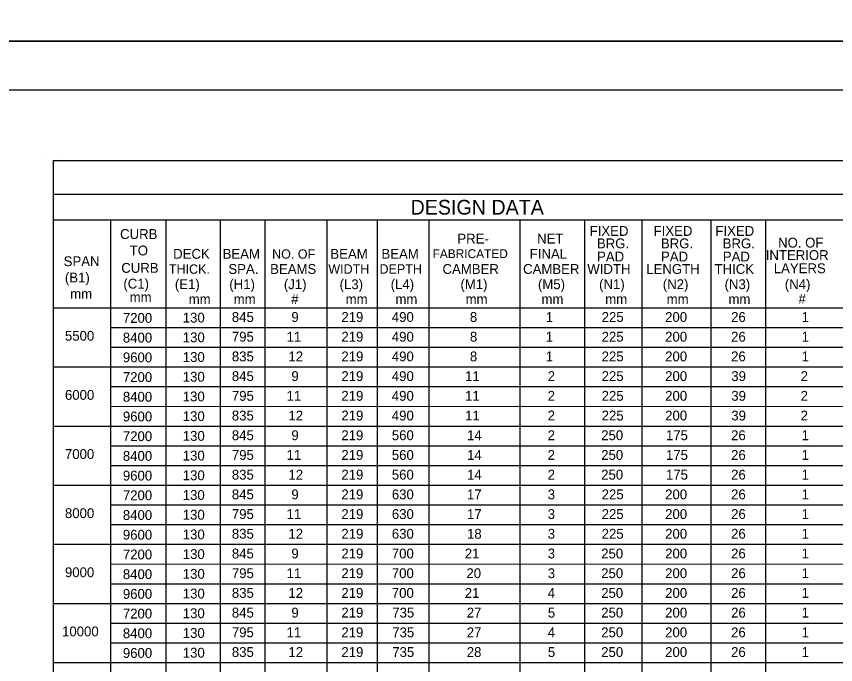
# Model space of a CAD drawing. Extents: x -5022 to -159, y 1126 to 7226.
# Drawn here: x -4612.3 to -4362.8, y 3906 to 4103.3 of the extents above; entities that cross this region are included whole.
import ezdxf

# ---------------------------------------------------------------- set-up
doc = ezdxf.new("R2010")
doc.units = 0
for name, color, linetype in [('2', 7, 'Continuous'), ('3', 7, 'Continuous'), ('PLT-BNDY', 7, 'Continuous')]:
    doc.layers.add(name, color=color, linetype=linetype)

msp = doc.modelspace()

# ---------------------------------------------------------------- linework, layer by layer
at = {"layer": '2'}
for p, q in [((-3855.13, 4080.81), (-4641.13, 4080.81)), ((-4603.08, 4061.37), (-4603.08, 4061.37)), ((-4599.68, 4060.79), (-4599.68, 4060.79))]:
    msp.add_line(p, q, dxfattribs=at)
at = {"layer": '3'}
for p, q in [((-4601.11, 4059.4), (-4601.11, 3708.59)), ((-4601.11, 4059.4), (-3886.2, 4059.4)), ((-4600.86, 4049.23), (-3886.2, 4049.23)), ((-4601.11, 4041.41), (-3886.2, 4041.41)), ((-4583.63, 4041.41), (-4583.63, 3708.59)), ((-4566.84, 4041.41), (-4566.84, 3708.59)), ((-4550.27, 4041.41), (-4550.27, 3708.59)), ((-4536.64, 4041.41), (-4536.64, 3708.59)), ((-4517.79, 4041.41), (-4517.79, 3708.59)), ((-4502.48, 4041.41), (-4502.48, 3708.59)), ((-4486.68, 4041.41), (-4486.68, 3708.59)), ((-4458.97, 4041.41), (-4458.97, 3708.59)), ((-4439.28, 4041.41), (-4439.28, 3708.59)), ((-4421.82, 4041.41), (-4421.82, 3708.59)), ((-4400.82, 4041.41), (-4400.82, 3708.59)), ((-4384.18, 4041.41), (-4384.18, 3708.59)), ((-4601.11, 4014.6), (-3886.2, 4014.6)), ((-4583.63, 4008.6), (-3886.2, 4008.6)), ((-4583.63, 4002.6), (-3886.2, 4002.6)), ((-4601.11, 3996.6), (-3886.2, 3996.6)), ((-4583.63, 3990.59), (-3886.2, 3990.6)), ((-4583.63, 3984.59), (-3886.2, 3984.6)), ((-4601.11, 3978.59), (-3886.2, 3978.6)), ((-4583.63, 3972.59), (-3886.2, 3972.6)), ((-4583.63, 3966.6), (-3886.2, 3966.6)), ((-4601.11, 3960.6), (-3886.2, 3960.6)), ((-4583.63, 3954.59), (-3886.2, 3954.6)), ((-4583.63, 3948.59), (-3886.2, 3948.6)), ((-4601.11, 3942.59), (-3886.2, 3942.6)), ((-4583.63, 3936.59), (-3886.2, 3936.6)), ((-4583.63, 3930.59), (-3886.2, 3930.59)), ((-4601.11, 3924.59), (-3886.2, 3924.59)), ((-4583.63, 3918.59), (-3886.2, 3918.59)), ((-4583.63, 3912.59), (-3886.2, 3912.6)), ((-4601.11, 3906.59), (-3886.2, 3906.59))]:
    msp.add_line(p, q, dxfattribs=at)
at = {"layer": 'PLT-BNDY'}
for points in [[(-4681.13, 4689.81), (-3840.13, 4689.81), (-3840.13, 4095.81), (-4681.13, 4095.81)], [(-4681.13, 4095.81), (-3840.13, 4095.81), (-3840.13, 3501.81), (-4681.13, 3501.81)]]:
    msp.add_lwpolyline(points, close=True, dxfattribs=at)

# ---------------------------------------------------------------- texts
at = {"layer": '2'}
for s, height, p in [('DESIGN DATA', 4.4793, (-4492.26, 4042.97)), ('CURB', 3, (-4580.74, 4035.54)), ('FIXED', 3, (-4437.7, 4036.49)), ('FIXED', 3, (-4418.22, 4036.49)), ('FIXED', 3, (-4399.4, 4036.49)), ('PRE-', 3, (-4478.01, 4034.15)), ('NET', 3, (-4453.71, 4034.15)), ('BRG.', 3, (-4435.49, 4032.7)), ('BRG.', 3, (-4416, 4032.7)), ('BRG.', 3, (-4397.19, 4032.7)), ('NO. OF', 3, (-4380.31, 4032.93)), ('TO', 3, (-4577.81, 4030.54)), ('SPAN', 3, (-4597.93, 4027.27)), ('DECK', 3, (-4564.57, 4029.52)), ('BEAM', 3, (-4549.51, 4029.52)), ('NO. OF', 2.85, (-4534.44, 4029.54)), ('BEAM', 3, (-4516.69, 4029.52)), ('BEAM', 3, (-4501.13, 4029.52)), ('FABRICATED', 2.708, (-4485.56, 4029.72)), ('FINAL', 3, (-4455.96, 4029.52)), ('PAD', 3, (-4435.45, 4028.69)), ('PAD', 3, (-4415.97, 4028.69)), ('PAD', 3, (-4397.15, 4028.69)), ('INTERIOR', 3, (-4384.07, 4029.14)), ('CURB', 3, (-4580.38, 4025.24)), ('THICK.', 2.85, (-4565.87, 4024.95)), ('SPA.', 3, (-4547.76, 4024.9)), ('BEAMS', 3, (-4535.03, 4024.9)), ('WIDTH', 2.85, (-4517.31, 4024.97)), ('DEPTH', 2.85, (-4501.72, 4024.98)), ('CAMBER', 3, (-4482.53, 4024.9)), ('CAMBER', 3, (-4457.98, 4024.9)), ('WIDTH', 3, (-4438.42, 4024.9)), ('LENGTH', 3, (-4420.46, 4024.9)), ('THICK', 3, (-4399.67, 4024.9)), ('LAYERS', 3, (-4381.63, 4025.13)), ('(B1)', 3, (-4597.56, 4022.3)), ('(C1)', 3, (-4579.75, 4020.44)), ('(E1)', 3, (-4564.06, 4020.27)), ('(H1)', 3, (-4547.47, 4020.27)), ('(J1)', 3, (-4530.86, 4020.27)), ('(L3)', 3, (-4513.88, 4020.27)), ('(L4)', 3, (-4498.32, 4020.27)), ('(M1)', 3, (-4477.07, 4020.27)), ('(M5)', 3, (-4453.46, 4020.27)), ('(N1)', 3, (-4434.83, 4020.27)), ('(N2)', 3, (-4415.43, 4020.27)), ('(N3)', 3, (-4396.61, 4020.27)), ('(N4)', 3, (-4378.27, 4020.27)), ('mm', 3, (-4595.94, 4017.33)), ('mm', 3, (-4577.84, 4016.34)), ('mm', 3, (-4559.83, 4015.74)), ('mm', 3, (-4546.13, 4015.74)), ('#', 3, (-4528.62, 4015.74)), ('mm', 3, (-4512.03, 4015.74)), ('mm', 3, (-4496.87, 4015.74)), ('mm', 3, (-4475.5, 4015.74)), ('mm', 3, (-4452.38, 4015.74)), ('mm', 3, (-4432.96, 4015.74)), ('mm', 3, (-4414.25, 4015.74)), ('mm', 3, (-4395.43, 4015.74)), ('#', 3, (-4374.09, 4015.85)), ('7200', 3, (-4579.9, 4010.01)), ('130', 3, (-4561.65, 4010.1)), ('845', 3, (-4546.7, 4010.29)), ('9', 3, (-4528.57, 4010.29)), ('219', 3, (-4513.34, 4010.29)), ('490', 3, (-4497.97, 4010.29)), ('8', 3, (-4474.18, 4010.29)), ('1', 3, (-4451.07, 4010.29)), ('225', 3, (-4434.05, 4010.29)), ('200', 3, (-4414.71, 4010.29)), ('26', 3, (-4394.62, 4010.29)), ('1', 3, (-4373.15, 4010.29)), ('5500', 3, (-4597.54, 4004.57)), ('8400', 3, (-4579.9, 4004.01)), ('130', 3, (-4561.65, 4004.1)), ('795', 3, (-4546.7, 4004.29)), ('11', 3, (-4530.04, 4004.29)), ('219', 3, (-4513.34, 4004.29)), ('490', 3, (-4497.97, 4004.29)), ('8', 3, (-4474.18, 4004.29)), ('1', 3, (-4451.07, 4004.29)), ('225', 3, (-4434.05, 4004.29)), ('200', 3, (-4414.71, 4004.29)), ('26', 3, (-4394.62, 4004.29)), ('1', 3, (-4373.15, 4004.29)), ('9600', 3, (-4579.9, 3998)), ('130', 3, (-4561.65, 3998.1)), ('835', 3, (-4546.7, 3998.29)), ('12', 3, (-4529.46, 3998.29)), ('219', 3, (-4513.34, 3998.29)), ('490', 3, (-4497.97, 3998.29)), ('8', 3, (-4474.18, 3998.29)), ('1', 3, (-4451.07, 3998.29)), ('225', 3, (-4434.05, 3998.29)), ('200', 3, (-4414.71, 3998.29)), ('26', 3, (-4394.62, 3998.29)), ('1', 3, (-4373.15, 3998.29)), ('845', 3, (-4546.7, 3992.29)), ('9', 3, (-4528.57, 3992.29)), ('219', 3, (-4513.34, 3992.29)), ('490', 3, (-4497.97, 3992.29)), ('11', 3, (-4475.65, 3992.29)), ('2', 3, (-4450.5, 3992.29)), ('225', 3, (-4434.05, 3992.29)), ('200', 3, (-4414.71, 3992.29)), ('39', 3, (-4394.56, 3992.29)), ('2', 3, (-4373.43, 3992.29)), ('7200', 3, (-4579.9, 3992)), ('130', 3, (-4561.65, 3992.1)), ('6000', 3, (-4597.54, 3986.57)), ('8400', 3, (-4579.9, 3986)), ('130', 3, (-4561.65, 3986.1)), ('795', 3, (-4546.7, 3986.29)), ('11', 3, (-4530.04, 3986.29)), ('219', 3, (-4513.34, 3986.29)), ('490', 3, (-4497.97, 3986.29)), ('11', 3, (-4475.65, 3986.29)), ('2', 3, (-4450.5, 3986.29)), ('225', 3, (-4434.05, 3986.29)), ('200', 3, (-4414.71, 3986.29)), ('39', 3, (-4394.56, 3986.29)), ('2', 3, (-4373.43, 3986.29)), ('9600', 3, (-4579.9, 3980)), ('130', 3, (-4561.65, 3980.09)), ('835', 3, (-4546.7, 3980.29)), ('12', 3, (-4529.46, 3980.29)), ('219', 3, (-4513.34, 3980.29)), ('490', 3, (-4497.97, 3980.29)), ('11', 3, (-4475.65, 3980.29)), ('2', 3, (-4450.5, 3980.29)), ('225', 3, (-4434.05, 3980.29)), ('200', 3, (-4414.71, 3980.29)), ('39', 3, (-4394.56, 3980.29)), ('2', 3, (-4373.43, 3980.29)), ('7200', 3, (-4579.9, 3974)), ('130', 3, (-4561.65, 3974.1)), ('845', 3, (-4546.7, 3974.29)), ('9', 3, (-4528.57, 3974.29)), ('219', 3, (-4513.34, 3974.29)), ('560', 3, (-4497.97, 3974.29)), ('14', 3, (-4475.05, 3974.29)), ('2', 3, (-4450.5, 3974.29)), ('250', 3, (-4434.19, 3974.29)), ('175', 3, (-4414.47, 3974.29)), ('26', 3, (-4394.62, 3974.29)), ('1', 3, (-4373.15, 3974.29)), ('7000', 3, (-4597.54, 3968.57)), ('8400', 3, (-4579.9, 3968)), ('130', 3, (-4561.65, 3968.1)), ('795', 3, (-4546.7, 3968.29)), ('11', 3, (-4530.04, 3968.29)), ('219', 3, (-4513.34, 3968.29)), ('560', 3, (-4497.97, 3968.29)), ('14', 3, (-4475.05, 3968.29)), ('2', 3, (-4450.5, 3968.29)), ('250', 3, (-4434.19, 3968.29)), ('175', 3, (-4414.47, 3968.29)), ('26', 3, (-4394.62, 3968.29)), ('1', 3, (-4373.15, 3968.29)), ('835', 3, (-4546.7, 3962.29)), ('12', 3, (-4529.46, 3962.29)), ('219', 3, (-4513.34, 3962.29)), ('560', 3, (-4497.97, 3962.29)), ('2', 3, (-4450.5, 3962.29)), ('250', 3, (-4434.19, 3962.29)), ('26', 3, (-4394.62, 3962.29)), ('9600', 3, (-4579.9, 3962)), ('130', 3, (-4561.65, 3962.1)), ('14', 3, (-4475.05, 3962.29)), ('175', 3, (-4414.47, 3962.29)), ('1', 3, (-4373.15, 3962.29)), ('7200', 3, (-4579.9, 3956)), ('130', 3, (-4561.65, 3956.1)), ('845', 3, (-4546.7, 3956.29)), ('9', 3, (-4528.57, 3956.29)), ('219', 3, (-4513.34, 3956.29)), ('630', 3, (-4497.97, 3956.29)), ('17', 3, (-4475.07, 3956.29)), ('3', 3, (-4450.48, 3956.29)), ('225', 3, (-4434.05, 3956.29)), ('200', 3, (-4414.71, 3956.29)), ('26', 3, (-4394.62, 3956.29)), ('1', 3, (-4373.15, 3956.29)), ('8000', 3, (-4597.54, 3950.57)), ('8400', 3, (-4579.9, 3950)), ('130', 3, (-4561.65, 3950.09)), ('795', 3, (-4546.7, 3950.29)), ('11', 3, (-4530.04, 3950.29)), ('219', 3, (-4513.34, 3950.29)), ('630', 3, (-4497.97, 3950.29)), ('17', 3, (-4475.07, 3950.29)), ('3', 3, (-4450.48, 3950.29)), ('225', 3, (-4434.05, 3950.29)), ('200', 3, (-4414.71, 3950.29)), ('26', 3, (-4394.62, 3950.29)), ('1', 3, (-4373.15, 3950.29)), ('9600', 3, (-4579.9, 3944)), ('130', 3, (-4561.65, 3944.09)), ('835', 3, (-4546.7, 3944.29)), ('12', 3, (-4529.46, 3944.29)), ('219', 3, (-4513.34, 3944.29)), ('630', 3, (-4497.97, 3944.29)), ('18', 3, (-4475.06, 3944.29)), ('3', 3, (-4450.48, 3944.29)), ('225', 3, (-4434.05, 3944.29)), ('200', 3, (-4414.71, 3944.29)), ('26', 3, (-4394.62, 3944.29)), ('1', 3, (-4373.15, 3944.29)), ('7200', 3, (-4579.9, 3938)), ('130', 3, (-4561.65, 3938.1)), ('845', 3, (-4546.7, 3938.29)), ('9', 3, (-4528.57, 3938.29)), ('219', 3, (-4513.34, 3938.29)), ('700', 3, (-4497.97, 3938.29)), ('21', 3, (-4475.74, 3938.29)), ('3', 3, (-4450.48, 3938.29)), ('250', 3, (-4434.19, 3938.29)), ('200', 3, (-4414.71, 3938.29)), ('26', 3, (-4394.62, 3938.29)), ('1', 3, (-4373.15, 3938.29)), ('9000', 3, (-4597.54, 3932.57)), ('8400', 3, (-4579.9, 3932)), ('130', 3, (-4561.65, 3932.1)), ('795', 3, (-4546.7, 3932.29)), ('11', 3, (-4530.04, 3932.29)), ('219', 3, (-4513.34, 3932.29)), ('700', 3, (-4497.97, 3932.29)), ('20', 3, (-4475.25, 3932.29)), ('3', 3, (-4450.48, 3932.29)), ('250', 3, (-4434.19, 3932.29)), ('200', 3, (-4414.71, 3932.29)), ('26', 3, (-4394.62, 3932.29)), ('1', 3, (-4373.15, 3932.29)), ('9600', 3, (-4579.9, 3926)), ('130', 3, (-4561.65, 3926.09)), ('835', 3, (-4546.7, 3926.29)), ('12', 3, (-4529.46, 3926.29)), ('219', 3, (-4513.34, 3926.29)), ('700', 3, (-4497.97, 3926.29)), ('21', 3, (-4475.74, 3926.29)), ('4', 3, (-4450.47, 3926.29)), ('250', 3, (-4434.19, 3926.29)), ('200', 3, (-4414.71, 3926.29)), ('26', 3, (-4394.62, 3926.29)), ('1', 3, (-4373.15, 3926.29)), ('7200', 3, (-4579.9, 3920)), ('130', 3, (-4561.65, 3920.09)), ('845', 3, (-4546.7, 3920.29)), ('9', 3, (-4528.57, 3920.29)), ('219', 3, (-4513.34, 3920.29)), ('735', 3, (-4497.83, 3920.29)), ('27', 3, (-4475.15, 3920.29)), ('5', 3, (-4450.44, 3920.29)), ('250', 3, (-4434.19, 3920.29)), ('200', 3, (-4414.71, 3920.29)), ('26', 3, (-4394.62, 3920.29)), ('1', 3, (-4373.15, 3920.29)), ('10000', 3, (-4598.42, 3914.57)), ('8400', 3, (-4579.9, 3914)), ('130', 3, (-4561.65, 3914.09)), ('795', 3, (-4546.7, 3914.29)), ('11', 3, (-4530.04, 3914.29)), ('219', 3, (-4513.34, 3914.29)), ('735', 3, (-4497.83, 3914.29)), ('27', 3, (-4475.15, 3914.29)), ('4', 3, (-4450.47, 3914.29)), ('250', 3, (-4434.19, 3914.29)), ('200', 3, (-4414.71, 3914.29)), ('26', 3, (-4394.62, 3914.29)), ('1', 3, (-4373.15, 3914.29)), ('9600', 3, (-4579.9, 3908)), ('130', 3, (-4561.65, 3908.09)), ('835', 3, (-4546.7, 3908.29)), ('12', 3, (-4529.46, 3908.29)), ('219', 3, (-4513.34, 3908.29)), ('735', 3, (-4497.83, 3908.29)), ('28', 3, (-4475.15, 3908.29)), ('5', 3, (-4450.44, 3908.29)), ('250', 3, (-4434.19, 3908.29)), ('200', 3, (-4414.71, 3908.29)), ('26', 3, (-4394.62, 3908.29)), ('1', 3, (-4373.15, 3908.29))]:
    msp.add_text(s, height=height, dxfattribs=at).set_placement(p)

doc.saveas('drawing.dxf')
